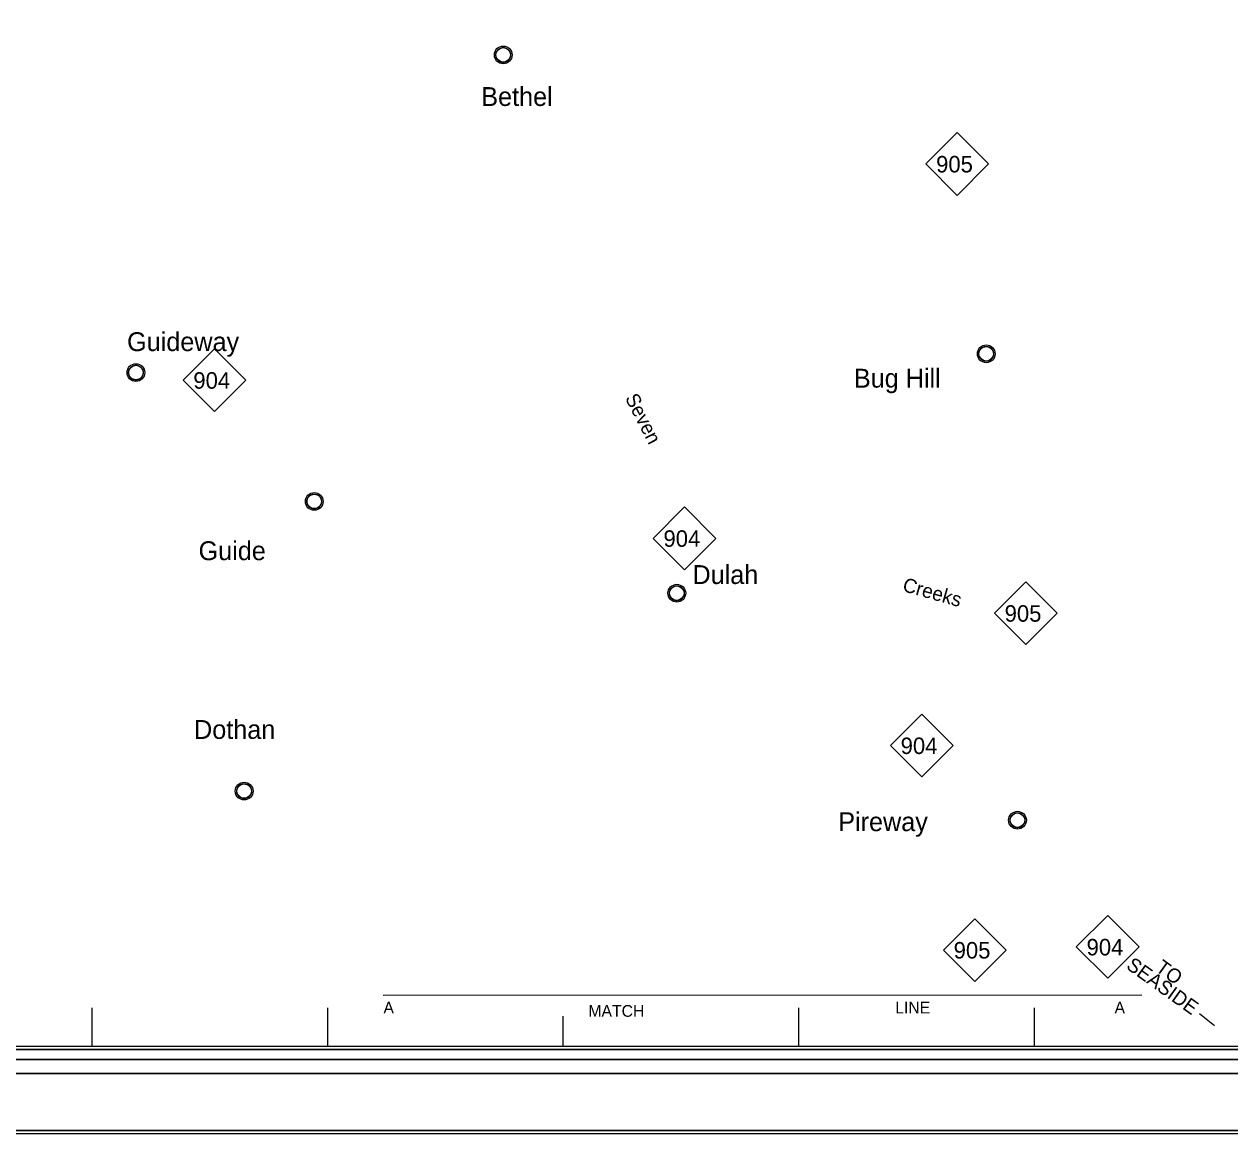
# Model space of a CAD drawing. Extents: x 5197761 to 5514561, y 1890130 to 2080942.
# Drawn here: x 5297901 to 5349083, y 1890130 to 1937242 of the extents above; entities that cross this region are included whole.
import ezdxf

# ---------------------------------------------------------------- set-up
doc = ezdxf.new("R2010")
doc.units = 0
for name, color, linetype in [('Exist Civil Demographics Community CELL', 7, 'Continuous'), ('Exist Civil Demographics Community Label', 7, 'Continuous'), ('Exist Hydrographic Creek Single Shore Label', 7, 'Continuous'), ('Exist Road Primary NC Shield CELL', 7, 'Continuous'), ('Exist Road Primary NC Shield Number Label', 7, 'Continuous'), ('Map Preparation Base StatePlane Tick Mark', 7, 'Continuous'), ('Map Preparation Border Antique Large Shape', 7, 'Continuous'), ('Map Preparation Border Antique Small Shape', 7, 'Continuous'), ('Map Preparation Border Black Inside Shape', 7, 'Continuous'), ('Map Preparation Border Black Middle Shape', 7, 'Continuous'), ('Map Preparation Border Black Outside Shape', 7, 'Continuous'), ('Map Preparation County Match Line', 7, 'Continuous'), ('Map Preparation County Match Line Label', 7, 'Continuous'), ('Map Preparation Destination Label', 7, 'Continuous')]:
    doc.layers.add(name, color=color, linetype=linetype)

msp = doc.modelspace()

# ---------------------------------------------------------------- linework, layer by layer
at = {"layer": 'Exist Civil Demographics Community CELL'}
for points in [[(5317928, 1935984), (5317932, 1936007), (5317939, 1936033), (5317951, 1936062), (5317963, 1936085), (5317976, 1936108), (5317991, 1936128), (5318007, 1936146), (5318025, 1936164), (5318047, 1936182), (5318069, 1936197), (5318089, 1936208), (5318109, 1936218), (5318131, 1936227), (5318153, 1936235), (5318171, 1936239), (5318190, 1936242), (5318206, 1936245), (5318232, 1936246), (5318250, 1936246), (5318272, 1936245), (5318292, 1936242), (5318312, 1936238), (5318332, 1936232), (5318352, 1936225), (5318379, 1936213), (5318404, 1936199), (5318424, 1936185), (5318445, 1936169), (5318458, 1936156), (5318475, 1936139), (5318490, 1936120), (5318502, 1936101), (5318515, 1936081), (5318525, 1936061), (5318533, 1936041), (5318539, 1936021), (5318544, 1936002), (5318549, 1935978), (5318551, 1935959), (5318552, 1935935), (5318551, 1935912), (5318549, 1935889), (5318545, 1935867), (5318539, 1935843), (5318531, 1935819), (5318522, 1935799), (5318509, 1935775), (5318496, 1935754), (5318482, 1935735), (5318466, 1935716), (5318444, 1935696), (5318424, 1935680), (5318404, 1935666), (5318387, 1935656), (5318360, 1935643), (5318331, 1935632), (5318307, 1935626), (5318281, 1935621), (5318263, 1935619), (5318245, 1935618), (5318223, 1935618), (5318206, 1935620), (5318183, 1935623), (5318160, 1935628), (5318141, 1935633), (5318121, 1935641), (5318102, 1935649), (5318087, 1935658), (5318059, 1935674), (5318037, 1935691), (5318017, 1935709), (5318000, 1935728), (5317987, 1935744), (5317975, 1935761), (5317959, 1935789), (5317952, 1935804), (5317945, 1935820), (5317934, 1935852), (5317928, 1935881), (5317926, 1935901), (5317924, 1935927), (5317924, 1935945), (5317926, 1935971)], [(5338429, 1923296), (5338433, 1923318), (5338441, 1923344), (5338452, 1923373), (5338464, 1923396), (5338477, 1923419), (5338492, 1923439), (5338508, 1923457), (5338527, 1923475), (5338549, 1923494), (5338570, 1923508), (5338590, 1923520), (5338610, 1923529), (5338632, 1923539), (5338654, 1923546), (5338672, 1923551), (5338691, 1923553), (5338708, 1923556), (5338733, 1923557), (5338751, 1923557), (5338774, 1923556), (5338793, 1923553), (5338813, 1923549), (5338833, 1923543), (5338854, 1923536), (5338880, 1923524), (5338905, 1923510), (5338925, 1923496), (5338946, 1923480), (5338959, 1923467), (5338976, 1923450), (5338991, 1923431), (5339004, 1923413), (5339016, 1923393), (5339026, 1923372), (5339034, 1923352), (5339040, 1923332), (5339045, 1923313), (5339050, 1923289), (5339052, 1923270), (5339053, 1923246), (5339053, 1923223), (5339050, 1923201), (5339047, 1923179), (5339040, 1923154), (5339032, 1923131), (5339023, 1923110), (5339011, 1923086), (5338998, 1923065), (5338984, 1923046), (5338967, 1923027), (5338946, 1923007), (5338926, 1922991), (5338906, 1922977), (5338888, 1922967), (5338861, 1922954), (5338832, 1922943), (5338809, 1922938), (5338782, 1922932), (5338764, 1922930), (5338747, 1922929), (5338724, 1922929), (5338707, 1922931), (5338685, 1922934), (5338661, 1922939), (5338642, 1922944), (5338622, 1922952), (5338603, 1922960), (5338588, 1922969), (5338561, 1922985), (5338538, 1923002), (5338519, 1923020), (5338501, 1923040), (5338488, 1923055), (5338476, 1923072), (5338460, 1923101), (5338453, 1923115), (5338446, 1923131), (5338436, 1923164), (5338429, 1923192), (5338427, 1923212), (5338425, 1923238), (5338425, 1923256), (5338427, 1923282)], [(5302336, 1922498), (5302340, 1922521), (5302347, 1922547), (5302359, 1922576), (5302371, 1922599), (5302384, 1922622), (5302399, 1922642), (5302415, 1922660), (5302433, 1922678), (5302455, 1922696), (5302477, 1922711), (5302497, 1922723), (5302517, 1922732), (5302539, 1922742), (5302561, 1922749), (5302579, 1922753), (5302598, 1922756), (5302615, 1922759), (5302640, 1922760), (5302658, 1922760), (5302680, 1922759), (5302700, 1922756), (5302720, 1922752), (5302740, 1922746), (5302760, 1922739), (5302787, 1922727), (5302812, 1922713), (5302832, 1922699), (5302853, 1922683), (5302866, 1922670), (5302883, 1922653), (5302898, 1922634), (5302910, 1922615), (5302923, 1922595), (5302933, 1922575), (5302941, 1922555), (5302947, 1922535), (5302952, 1922516), (5302957, 1922492), (5302959, 1922473), (5302960, 1922449), (5302959, 1922426), (5302957, 1922403), (5302953, 1922382), (5302947, 1922357), (5302939, 1922334), (5302930, 1922313), (5302917, 1922289), (5302904, 1922268), (5302891, 1922249), (5302874, 1922230), (5302852, 1922210), (5302832, 1922194), (5302812, 1922180), (5302795, 1922170), (5302768, 1922157), (5302739, 1922146), (5302715, 1922140), (5302689, 1922135), (5302671, 1922133), (5302653, 1922132), (5302631, 1922132), (5302614, 1922134), (5302591, 1922137), (5302568, 1922142), (5302549, 1922147), (5302529, 1922155), (5302510, 1922163), (5302495, 1922172), (5302467, 1922188), (5302445, 1922205), (5302425, 1922223), (5302408, 1922243), (5302395, 1922258), (5302383, 1922275), (5302367, 1922303), (5302360, 1922318), (5302353, 1922334), (5302342, 1922366), (5302336, 1922395), (5302334, 1922415), (5302332, 1922441), (5302332, 1922459), (5302334, 1922485)], [(5309906, 1917029), (5309910, 1917051), (5309917, 1917077), (5309929, 1917106), (5309941, 1917129), (5309954, 1917152), (5309969, 1917172), (5309985, 1917190), (5310003, 1917208), (5310025, 1917227), (5310047, 1917241), (5310067, 1917253), (5310087, 1917263), (5310109, 1917272), (5310131, 1917279), (5310149, 1917284), (5310168, 1917287), (5310184, 1917289), (5310210, 1917290), (5310228, 1917290), (5310250, 1917289), (5310270, 1917286), (5310290, 1917282), (5310310, 1917277), (5310330, 1917269), (5310357, 1917257), (5310382, 1917243), (5310402, 1917229), (5310423, 1917213), (5310436, 1917200), (5310453, 1917183), (5310468, 1917164), (5310480, 1917146), (5310493, 1917126), (5310503, 1917105), (5310511, 1917085), (5310517, 1917065), (5310522, 1917047), (5310527, 1917022), (5310529, 1917004), (5310530, 1916980), (5310529, 1916956), (5310527, 1916934), (5310523, 1916912), (5310517, 1916887), (5310509, 1916864), (5310500, 1916843), (5310487, 1916819), (5310474, 1916798), (5310460, 1916779), (5310444, 1916760), (5310422, 1916741), (5310402, 1916724), (5310382, 1916710), (5310365, 1916700), (5310338, 1916687), (5310309, 1916676), (5310285, 1916671), (5310259, 1916665), (5310241, 1916664), (5310223, 1916662), (5310201, 1916662), (5310184, 1916664), (5310161, 1916667), (5310138, 1916672), (5310119, 1916677), (5310099, 1916685), (5310080, 1916693), (5310065, 1916702), (5310037, 1916718), (5310015, 1916735), (5309995, 1916753), (5309977, 1916773), (5309965, 1916789), (5309953, 1916805), (5309936, 1916834), (5309930, 1916848), (5309923, 1916864), (5309912, 1916897), (5309906, 1916925), (5309903, 1916945), (5309902, 1916971), (5309902, 1916990), (5309904, 1917015)], [(5325296, 1913133), (5325300, 1913155), (5325307, 1913181), (5325319, 1913210), (5325330, 1913233), (5325344, 1913256), (5325359, 1913276), (5325375, 1913294), (5325393, 1913312), (5325415, 1913331), (5325437, 1913345), (5325456, 1913357), (5325477, 1913367), (5325498, 1913376), (5325521, 1913383), (5325538, 1913388), (5325558, 1913391), (5325574, 1913393), (5325600, 1913395), (5325617, 1913394), (5325640, 1913393), (5325660, 1913390), (5325679, 1913386), (5325699, 1913381), (5325720, 1913373), (5325747, 1913361), (5325772, 1913347), (5325792, 1913333), (5325813, 1913317), (5325826, 1913304), (5325842, 1913287), (5325858, 1913268), (5325870, 1913250), (5325883, 1913230), (5325892, 1913209), (5325900, 1913189), (5325907, 1913169), (5325912, 1913151), (5325916, 1913126), (5325919, 1913108), (5325920, 1913084), (5325919, 1913060), (5325917, 1913038), (5325913, 1913016), (5325906, 1912991), (5325899, 1912968), (5325890, 1912947), (5325877, 1912923), (5325864, 1912902), (5325850, 1912883), (5325833, 1912864), (5325812, 1912845), (5325792, 1912828), (5325772, 1912814), (5325755, 1912804), (5325727, 1912791), (5325699, 1912780), (5325675, 1912775), (5325649, 1912769), (5325631, 1912768), (5325613, 1912766), (5325591, 1912766), (5325574, 1912768), (5325551, 1912771), (5325527, 1912776), (5325509, 1912782), (5325488, 1912789), (5325470, 1912797), (5325454, 1912806), (5325427, 1912822), (5325405, 1912839), (5325385, 1912857), (5325367, 1912877), (5325354, 1912893), (5325343, 1912909), (5325326, 1912938), (5325319, 1912952), (5325312, 1912968), (5325302, 1913001), (5325296, 1913029), (5325293, 1913050), (5325292, 1913075), (5325292, 1913094), (5325294, 1913119)], [(5306930, 1904731), (5306934, 1904754), (5306941, 1904780), (5306953, 1904809), (5306965, 1904832), (5306978, 1904855), (5306993, 1904875), (5307009, 1904893), (5307027, 1904911), (5307049, 1904929), (5307071, 1904944), (5307091, 1904956), (5307111, 1904965), (5307133, 1904974), (5307155, 1904982), (5307172, 1904986), (5307192, 1904989), (5307208, 1904992), (5307234, 1904993), (5307252, 1904993), (5307274, 1904992), (5307294, 1904989), (5307313, 1904985), (5307333, 1904979), (5307354, 1904972), (5307381, 1904960), (5307406, 1904946), (5307426, 1904932), (5307447, 1904916), (5307460, 1904903), (5307476, 1904886), (5307492, 1904867), (5307504, 1904848), (5307517, 1904828), (5307527, 1904808), (5307535, 1904788), (5307541, 1904768), (5307546, 1904749), (5307550, 1904725), (5307553, 1904706), (5307554, 1904682), (5307553, 1904659), (5307551, 1904636), (5307547, 1904614), (5307541, 1904590), (5307533, 1904566), (5307524, 1904546), (5307511, 1904522), (5307498, 1904501), (5307484, 1904482), (5307467, 1904463), (5307446, 1904443), (5307426, 1904427), (5307406, 1904413), (5307389, 1904403), (5307362, 1904390), (5307333, 1904379), (5307309, 1904373), (5307283, 1904368), (5307265, 1904366), (5307247, 1904365), (5307225, 1904365), (5307208, 1904367), (5307185, 1904370), (5307161, 1904375), (5307143, 1904380), (5307122, 1904388), (5307104, 1904396), (5307088, 1904405), (5307061, 1904421), (5307039, 1904438), (5307019, 1904456), (5307001, 1904475), (5306989, 1904491), (5306977, 1904508), (5306960, 1904536), (5306954, 1904551), (5306947, 1904567), (5306936, 1904599), (5306930, 1904628), (5306927, 1904648), (5306926, 1904674), (5306926, 1904692), (5306928, 1904718)], [(5339757, 1903496), (5339761, 1903518), (5339768, 1903544), (5339779, 1903573), (5339791, 1903596), (5339805, 1903619), (5339820, 1903639), (5339835, 1903657), (5339854, 1903675), (5339876, 1903694), (5339898, 1903708), (5339917, 1903720), (5339937, 1903729), (5339959, 1903739), (5339982, 1903746), (5339999, 1903751), (5340018, 1903753), (5340035, 1903756), (5340060, 1903757), (5340078, 1903757), (5340101, 1903756), (5340120, 1903753), (5340140, 1903749), (5340160, 1903743), (5340181, 1903736), (5340207, 1903724), (5340232, 1903710), (5340253, 1903696), (5340273, 1903680), (5340287, 1903667), (5340303, 1903650), (5340319, 1903631), (5340331, 1903613), (5340343, 1903593), (5340353, 1903572), (5340361, 1903552), (5340368, 1903532), (5340373, 1903513), (5340377, 1903489), (5340380, 1903470), (5340381, 1903446), (5340380, 1903423), (5340378, 1903401), (5340374, 1903379), (5340367, 1903354), (5340360, 1903331), (5340351, 1903310), (5340338, 1903286), (5340325, 1903265), (5340311, 1903246), (5340294, 1903227), (5340273, 1903207), (5340253, 1903191), (5340233, 1903177), (5340216, 1903167), (5340188, 1903154), (5340160, 1903143), (5340136, 1903138), (5340109, 1903132), (5340092, 1903130), (5340074, 1903129), (5340051, 1903129), (5340034, 1903131), (5340012, 1903134), (5339988, 1903139), (5339970, 1903144), (5339949, 1903152), (5339931, 1903160), (5339915, 1903169), (5339888, 1903185), (5339865, 1903202), (5339846, 1903220), (5339828, 1903240), (5339815, 1903255), (5339803, 1903272), (5339787, 1903301), (5339780, 1903315), (5339773, 1903331), (5339763, 1903364), (5339757, 1903392), (5339754, 1903412), (5339753, 1903438), (5339752, 1903456), (5339755, 1903482)]]:
    msp.add_lwpolyline(points, close=True, dxfattribs=at)
for centre, radius in [((5318239, 1935935), 377), ((5318238, 1935936), 307), ((5338740, 1923246), 377), ((5338739, 1923247), 307), ((5302647, 1922449), 377), ((5302646, 1922450), 307), ((5310217, 1916979), 377), ((5310216, 1916980), 307), ((5325606, 1913083), 377), ((5325605, 1913084), 307), ((5307241, 1904682), 377), ((5307240, 1904683), 307), ((5340067, 1903446), 377), ((5340066, 1903447), 307)]:
    msp.add_circle(centre, radius, dxfattribs=at)
at = {"layer": 'Exist Road Primary NC Shield CELL'}
for points in [[(5336176, 1931304), (5337508, 1932636), (5338840, 1931304), (5337508, 1929972)], [(5304647, 1922122), (5305979, 1923454), (5307311, 1922122), (5305979, 1920791)], [(5324604, 1915411), (5325936, 1916743), (5327268, 1915411), (5325936, 1914079)], [(5339086, 1912231), (5340418, 1913563), (5341750, 1912231), (5340418, 1910899)], [(5334671, 1906614), (5336003, 1907946), (5337335, 1906614), (5336003, 1905282)], [(5342564, 1898066), (5343896, 1899398), (5345228, 1898066), (5343896, 1896734)], [(5336921, 1897934), (5338253, 1899266), (5339585, 1897934), (5338253, 1896602)]]:
    msp.add_lwpolyline(points, close=True, dxfattribs=at)
at = {"layer": 'Map Preparation Base StatePlane Tick Mark'}
for p, q in [((5300787, 1893858), (5300787, 1895484)), ((5310787, 1893858), (5310787, 1895484)), ((5330787, 1893858), (5330787, 1895484)), ((5340787, 1893858), (5340787, 1895484)), ((5320787, 1893858), (5320787, 1895126))]:
    msp.add_line(p, q, dxfattribs=at)
at = {"layer": 'Map Preparation Border Antique Large Shape'}
msp.add_lwpolyline([(5197907, 2074783), (5207205, 2074783), (5207205, 1892697), (5512539, 1892697), (5512539, 2072359), (5207205, 2072359), (5207205, 2074783), (5514414, 2074783), (5514414, 1890276), (5197907, 1890276)], close=True, dxfattribs=at)
at = {"layer": 'Map Preparation Border Antique Small Shape'}
msp.add_lwpolyline([(5207791, 2071720), (5208220, 2071720), (5208220, 1893712), (5511524, 1893712), (5511524, 2071291), (5208220, 2071291), (5208220, 2071720), (5207791, 2071720), (5511953, 2071720), (5511953, 1893283), (5208220, 1893283), (5207791, 1893283)], close=True, dxfattribs=at)
at = {"layer": 'Map Preparation Border Black Inside Shape'}
msp.add_lwpolyline([(5208220, 2071291), (5511524, 2071291), (5511524, 1893712), (5208366, 1893712), (5208366, 1893858), (5511378, 1893858), (5511378, 2071145), (5208366, 2071145), (5208366, 1893858), (5208366, 1893712), (5208220, 1893712), (5208220, 1893858)], close=True, dxfattribs=at)
at = {"layer": 'Map Preparation Border Black Middle Shape'}
msp.add_lwpolyline([(5207205, 2072359), (5512539, 2072359), (5512539, 1892697), (5511953, 1892697), (5207791, 1892697), (5207791, 1893283), (5511953, 1893283), (5511953, 2071720), (5207791, 2071720), (5207791, 1892697), (5207205, 1892697)], close=True, dxfattribs=at)
at = {"layer": 'Map Preparation Border Black Outside Shape'}
msp.add_lwpolyline([(5197761, 2074930), (5514561, 2074930), (5514561, 1890130), (5197907, 1890130), (5197907, 1890276), (5514414, 1890276), (5514414, 2074783), (5197907, 2074783), (5197907, 1890130), (5197761, 1890130)], close=True, dxfattribs=at)
at = {"layer": 'Map Preparation County Match Line'}
msp.add_line((5313146, 1896018), (5345344, 1896030), dxfattribs=at)
at = {"layer": 'Map Preparation Destination Label'}
msp.add_line((5348429, 1894715), (5347793, 1895231), dxfattribs=at)

# ---------------------------------------------------------------- texts
at = {"layer": 'Exist Civil Demographics Community Label'}
for s, p in [('Bethel', (5317305, 1933767)), ('Guideway', (5302272, 1923361)), ('Bug Hill', (5333123, 1921811)), ('Guide', (5305306, 1914486)), ('Dulah', (5326270, 1913474)), ('Dothan', (5305114, 1906898)), ('Pireway', (5332458, 1902982))]:
    msp.add_text(s, height=800, dxfattribs=at).set_placement(p)
at = {"layer": 'Exist Hydrographic Creek Single Shore Label'}
for s, rotation, p in [('Seven', 297.2536, (5323393, 1921371)), ('Creeks', 344.1663, (5335151, 1913184))]:
    msp.add_text(s, height=600, rotation=rotation, dxfattribs=at).set_placement(p)
at = {"layer": 'Exist Road Primary NC Shield Number Label'}
for s, p in [('905', (5336613, 1930945)), ('904', (5305084, 1921764)), ('904', (5325040, 1915052)), ('905', (5339522, 1911873)), ('904', (5335108, 1906255)), ('904', (5343001, 1897707)), ('905', (5337358, 1897575))]:
    msp.add_text(s, height=700, dxfattribs=at).set_placement(p)
at = {"layer": 'Map Preparation County Match Line Label'}
for s, p in [('A', (5313154, 1895241)), ('MATCH', (5321853, 1895100)), ('LINE', (5334877, 1895241)), ('A', (5344187, 1895241))]:
    msp.add_text(s, height=500, rotation=360, dxfattribs=at).set_placement(p)
at = {"layer": 'Map Preparation Destination Label'}
for s, p in [(' SEASIDE', (5344460, 1897313)), ('TO', (5345886, 1897077))]:
    msp.add_text(s, height=600, rotation=324.3129, dxfattribs=at).set_placement(p)

doc.saveas('drawing.dxf')
